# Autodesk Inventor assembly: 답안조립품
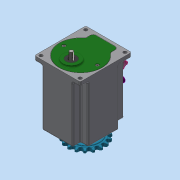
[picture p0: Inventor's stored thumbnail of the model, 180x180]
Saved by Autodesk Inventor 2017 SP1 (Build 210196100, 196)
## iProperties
Part Number: 답안조립품
Material: 일반
Document SubType Name: Assembly
Designer: MRC
Author: MRC
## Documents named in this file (16)
- C:\Users\MRC\Desktop\720212V1011\답안조립품.iam
- C:\Users\MRC\Desktop\720212V1011\멈춤나사 M3.ipt
- C:\Users\MRC\Desktop\720212V1011\메인 축.ipt
- C:\Users\MRC\Desktop\720212V1011\베어링 608.ipt
- C:\Users\MRC\Desktop\720212V1011\베어링 6003.ipt
- C:\Users\MRC\Desktop\720212V1011\본체.ipt
- C:\Users\MRC\Desktop\720212V1011\볼트 M4 x 10.ipt
- C:\Users\MRC\Desktop\720212V1011\부시.ipt
- C:\Users\MRC\Desktop\720212V1011\상부 캡.ipt
- C:\Users\MRC\Desktop\720212V1011\서브 축.ipt
- C:\Users\MRC\Desktop\720212V1011\스프로킷.ipt
- C:\Users\MRC\Desktop\720212V1011\슬라이더.ipt
- C:\Users\MRC\Desktop\720212V1011\오일 실 8 x 22 x 7.ipt
- C:\Users\MRC\Desktop\720212V1011\오일 실 17 x 32 x 8.ipt
- C:\Users\MRC\Desktop\720212V1011\커버.ipt
- C:\Users\MRC\Desktop\720212V1011\키 5 x 5.ipt
